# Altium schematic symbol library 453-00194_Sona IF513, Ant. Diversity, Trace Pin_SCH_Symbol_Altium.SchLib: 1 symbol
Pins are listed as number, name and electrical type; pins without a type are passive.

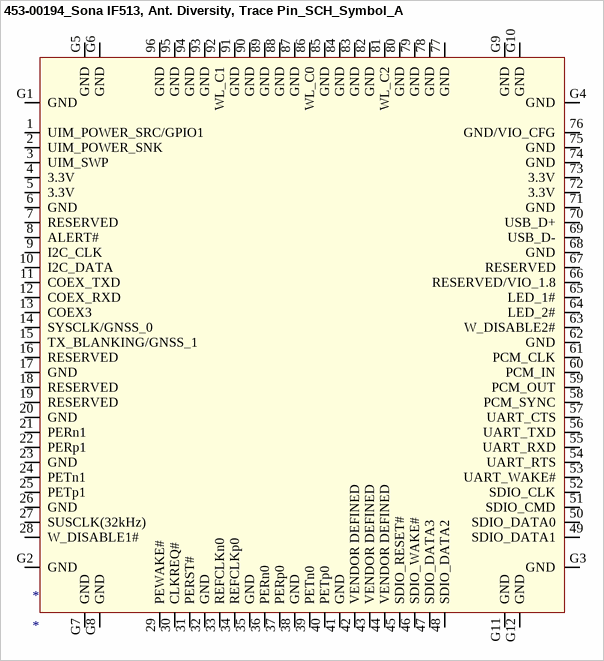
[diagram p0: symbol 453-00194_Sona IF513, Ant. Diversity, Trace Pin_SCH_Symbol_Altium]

## 453-00194_Sona IF513, Ant. Diversity, Trace Pin_SCH_Symbol_Altium
designator *
pins: 1 UIM_POWER_SRC/GPIO1, 2 UIM_POWER_SNK, 3 UIM_SWP, 4 3.3V, 5 3.3V, 6 GND, 7 RESERVED, 8 ALERT#, 9 I2C_CLK, 10 I2C_DATA, 11 COEX_TXD, 12 COEX_RXD, 13 COEX3, 14 SYSCLK/GNSS_0, 15 TX_BLANKING/GNSS_1, 16 RESERVED, 17 GND, 18 RESERVED, 19 RESERVED, 20 GND, 21 PERn1, 22 PERp1, 23 GND, 24 PETn1, 25 PETp1, 26 GND, 27 SUSCLK(32kHz), 28 W_DISABLE1#, 29 PEWAKE#, 30 CLKREQ#, 31 PERST#, 32 GND, 33 REFCLKn0, 34 REFCLKp0, 35 GND, 36 PERn0, 37 PERp0, 38 GND, 39 PETn0, 40 PETp0, 41 GND, 42 VENDOR DEFINED, 43 VENDOR DEFINED, 44 VENDOR DEFINED, 45 SDIO_RESET#, 46 SDIO_WAKE#, 47 SDIO_DATA3, 48 SDIO_DATA2, 49 SDIO_DATA1, 50 SDIO_DATA0, 51 SDIO_CMD, 52 SDIO_CLK, 53 UART_WAKE#, 54 UART_RTS, 55 UART_RXD, 56 UART_TXD, 57 UART_CTS, 58 PCM_SYNC, 59 PCM_OUT, 60 PCM_IN, 61 PCM_CLK, 62 GND, 63 W_DISABLE2#, 64 LED_2#, 65 LED_1#, 66 RESERVED/VIO_1.8, 67 RESERVED, 68 GND, 69 USB_D-, 70 USB_D+, 71 GND, 72 3.3V, 73 3.3V, 74 GND, 75 GND, 76 GND/VIO_CFG, 77 GND, 78 GND, 79 GND, 80 GND, 81 WL_C2, 82 GND, 83 GND, 84 GND, 85 GND, 86 WL_C0, 87 GND, 88 GND, 89 GND, 90 GND, 91 GND, 92 WL_C1, 93 GND, 94 GND, 95 GND, 96 GND, G1 GND, G2 GND, G3 GND, G4 GND, G5 GND, G6 GND, G7 GND, G8 GND, G9 GND, G10 GND, G11 GND, G12 GND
